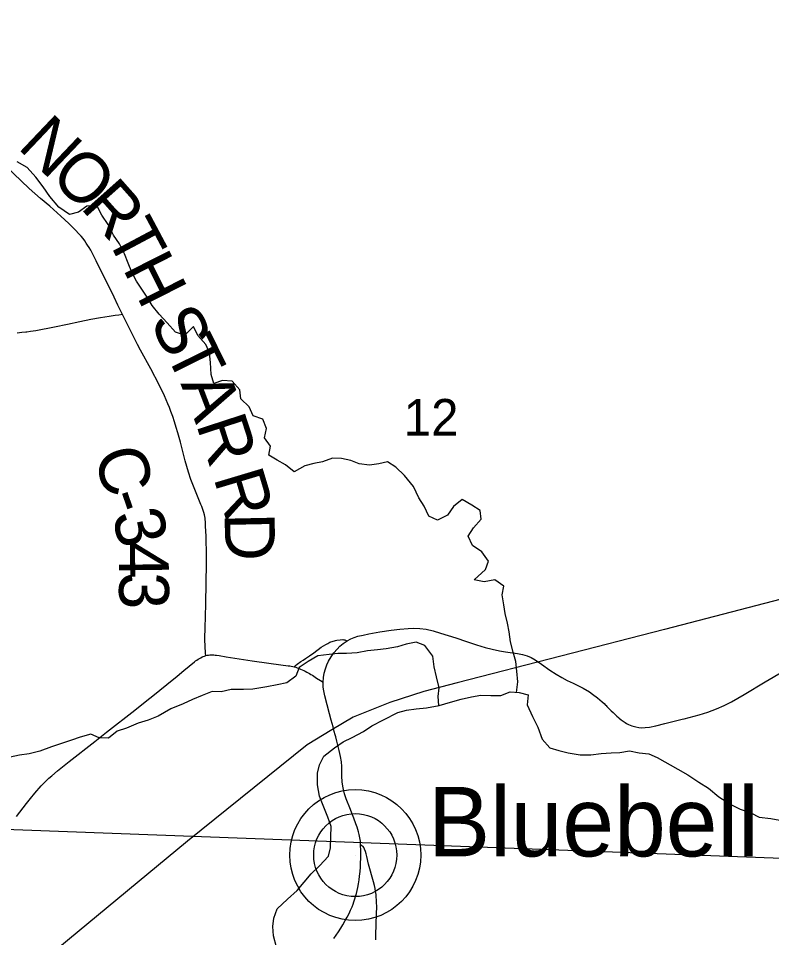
# Model space of a CAD drawing. Extents: x 0 to 34, y 0 to 22.
# Drawn here: x 26.138 to 26.994, y 18.613 to 19.658 of the extents above; entities that cross this region are included whole.
import ezdxf

# ---------------------------------------------------------------- set-up
doc = ezdxf.new("R2010")
doc.units = 0
for name, color, linetype in [('GM_X_Corporation', 7, 'Continuous'), ('GM_X_County_Road', 7, 'Continuous'), ('GM_X_County_Road_Text', 7, 'Continuous'), ('GM_X_Minor_River', 7, 'Continuous'), ('GM_X_Rail_Line', 7, 'Continuous'), ('GM_X_Section_Text', 7, 'Continuous'), ('GM_X_State_Route', 7, 'Continuous'), ('GM_X_Township_Road', 7, 'Continuous'), ('GM_X_Unincorporated', 7, 'Continuous'), ('GM_X_Unincorporated_Location', 7, 'Continuous'), ('GM_X_Unincorporated_Text', 7, 'Continuous')]:
    doc.layers.add(name, color=color, linetype=linetype)

msp = doc.modelspace()

# ---------------------------------------------------------------- linework, layer by layer
at = {"layer": 'GM_X_Corporation'}
msp.add_lwpolyline([(27.1321, 19.6957), (27.1305, 19.6616), (27.1072, 18.6988), (26.0916, 18.7368), (26.1009, 19.7362)], close=True, dxfattribs=at)
at = {"layer": 'GM_X_County_Road'}
for points in [[(26.2561, 19.3208), (26.2507, 19.3315), (26.2464, 19.3405), (26.2263, 19.3818), (26.2226, 19.3889), (26.2199, 19.3939), (26.2182, 19.397), (26.2164, 19.3999), (26.2149, 19.4022), (26.2132, 19.4045), (26.2112, 19.4072), (26.2089, 19.4099), (26.2061, 19.413), (26.203, 19.4164), (26.1951, 19.4244), (26.186, 19.4329), (26.1734, 19.4439), (26.163, 19.4528), (26.1499, 19.4643), (26.1233, 19.4897)], [(26.2561, 19.3208), (26.2518, 19.3203), (26.2477, 19.3197), (26.241, 19.3188), (26.2312, 19.3172), (26.2202, 19.3151), (26.2074, 19.3125), (26.1935, 19.3096), (26.1789, 19.3067), (26.1576, 19.3025), (26.1515, 19.3016), (26.1472, 19.301), (26.146, 19.3008), (26.1417, 19.3003), (26.1364, 19.2998)], [(26.3508, 18.9331), (26.3505, 18.9359), (26.3503, 18.9387), (26.3501, 18.9413), (26.35, 18.9448), (26.3498, 18.9504), (26.3498, 18.9547), (26.3499, 18.9627), (26.3505, 18.9794), (26.3508, 18.99), (26.3512, 19.0176), (26.3514, 19.0355), (26.3514, 19.0529), (26.3513, 19.0622), (26.3511, 19.069), (26.3508, 19.0747), (26.3505, 19.0803), (26.3503, 19.0857), (26.3501, 19.0876), (26.35, 19.0894), (26.3496, 19.0913), (26.3492, 19.0933), (26.3485, 19.0957), (26.3478, 19.0981), (26.347, 19.1002), (26.3461, 19.1027), (26.3452, 19.1051), (26.3421, 19.1125), (26.3389, 19.12), (26.3338, 19.1333), (26.3311, 19.1416), (26.3273, 19.1546), (26.3219, 19.1757), (26.319, 19.1865), (26.3172, 19.1926), (26.3151, 19.199), (26.3131, 19.205), (26.3111, 19.2108), (26.3094, 19.2153), (26.3077, 19.2195), (26.3037, 19.2286), (26.2976, 19.241), (26.2881, 19.2591), (26.2766, 19.2805), (26.2732, 19.287), (26.2659, 19.3014), (26.2614, 19.3102), (26.2561, 19.3208)], [(26.4511, 18.9205), (26.4526, 18.9218), (26.4544, 18.9233), (26.4562, 18.9247), (26.4574, 18.9255), (26.4586, 18.9263), (26.4612, 18.9279), (26.4639, 18.9297), (26.4687, 18.933), (26.4735, 18.9365), (26.482, 18.9426), (26.4872, 18.9458), (26.4895, 18.9471), (26.4906, 18.9477), (26.4917, 18.9483), (26.493, 18.9488), (26.4943, 18.9493), (26.4956, 18.9497), (26.4969, 18.9501), (26.4983, 18.9504), (26.4997, 18.9508), (26.5034, 18.9512), (26.5064, 18.9513), (26.5076, 18.9512), (26.5089, 18.951), (26.5103, 18.9505), (26.5115, 18.9501)], [(26.1354, 18.7502), (26.147, 18.7651), (26.1516, 18.7709), (26.1564, 18.7767), (26.1638, 18.785), (26.1698, 18.7912), (26.1725, 18.7938), (26.1757, 18.7966), (26.1823, 18.8023), (26.1954, 18.8127), (26.2247, 18.8357), (26.2379, 18.846), (26.2702, 18.8713), (26.2838, 18.8821), (26.2907, 18.8875), (26.3066, 18.9004), (26.3181, 18.9098), (26.3258, 18.9162), (26.3378, 18.926), (26.3392, 18.9271), (26.3406, 18.9281), (26.342, 18.9291), (26.3435, 18.93), (26.3449, 18.9308), (26.3465, 18.9316), (26.3478, 18.9321), (26.3491, 18.9326), (26.3508, 18.9331)], [(26.3508, 18.9331), (26.3523, 18.9335), (26.3539, 18.9337), (26.3553, 18.9339), (26.3567, 18.934), (26.3582, 18.934), (26.3598, 18.9339), (26.3613, 18.9337), (26.3627, 18.9335), (26.366, 18.9331), (26.374, 18.9319), (26.4034, 18.9273), (26.4388, 18.9224), (26.4416, 18.9221), (26.4445, 18.9217), (26.4462, 18.9215), (26.4478, 18.9212), (26.4495, 18.9209), (26.4511, 18.9205)], [(26.4511, 18.9205), (26.4529, 18.9199), (26.4547, 18.9193), (26.4567, 18.9185), (26.4584, 18.9177), (26.4602, 18.917), (26.4621, 18.9161), (26.4638, 18.9153), (26.4654, 18.9145), (26.4671, 18.9136), (26.4687, 18.9127), (26.4702, 18.9118), (26.4719, 18.9109), (26.4734, 18.9099), (26.4752, 18.9087), (26.4767, 18.9077), (26.4812, 18.9048), (26.4841, 18.9029)]]:
    msp.add_lwpolyline(points, dxfattribs=at)
at = {"layer": 'GM_X_Minor_River'}
for points in [[(26.7039, 18.8914), (26.7054, 18.9032), (26.7042, 18.9153), (26.703, 18.9263), (26.7002, 18.9372), (26.6971, 18.9489), (26.6955, 18.9603), (26.6935, 18.9701), (26.6911, 18.9811), (26.6895, 18.9909), (26.6876, 19.0023), (26.6894, 19.0121), (26.6791, 19.0192), (26.667, 19.0172), (26.6557, 19.0194), (26.6688, 19.0312), (26.6721, 19.0407), (26.6645, 19.0513), (26.6538, 19.0584), (26.6488, 19.0689), (26.6548, 19.0784), (26.6637, 19.0884), (26.6625, 19.0982), (26.653, 19.1042), (26.642, 19.1105), (26.6322, 19.1028), (26.6255, 19.0929), (26.6139, 19.0871), (26.6044, 19.0916), (26.599, 19.1029), (26.5929, 19.1127), (26.5867, 19.1255), (26.5764, 19.1379), (26.5668, 19.1472), (26.5573, 19.1536), (26.5472, 19.1512), (26.5366, 19.1496), (26.5252, 19.151), (26.5154, 19.155), (26.5048, 19.1572), (26.4949, 19.1575), (26.4832, 19.1536), (26.4734, 19.1516), (26.4633, 19.1488), (26.4512, 19.1419), (26.4413, 19.1501), (26.4318, 19.1553), (26.4223, 19.1612), (26.4241, 19.1711), (26.4176, 19.1809), (26.4198, 19.1915), (26.4155, 19.2021), (26.4045, 19.2058), (26.3999, 19.216), (26.3904, 19.2249), (26.3895, 19.2352), (26.3808, 19.2453), (26.3698, 19.2459), (26.36, 19.2424), (26.3569, 19.2526), (26.356, 19.2663), (26.3548, 19.2772), (26.3509, 19.287), (26.3417, 19.2972), (26.3367, 19.3074), (26.327, 19.2974), (26.3164, 19.3007), (26.3068, 19.3116), (26.2977, 19.3213), (26.2897, 19.3311), (26.2835, 19.3417), (26.272, 19.359), (26.2667, 19.3691), (26.2624, 19.3793), (26.2585, 19.3899), (26.2528, 19.4012), (26.2459, 19.411), (26.2397, 19.4234), (26.2324, 19.4339), (26.2267, 19.4449), (26.2157, 19.444), (26.206, 19.4371), (26.1958, 19.4347), (26.1836, 19.4429), (26.1733, 19.4549), (26.166, 19.4662), (26.1576, 19.4771), (26.1477, 19.488), (26.1363, 19.4943)], [(26.6157, 18.8764), (26.6149, 18.8867), (26.6159, 18.8966), (26.6131, 18.909), (26.6104, 18.9204), (26.6088, 18.9325), (26.5996, 18.9445), (26.5897, 18.9486), (26.5784, 18.9462), (26.5686, 18.943), (26.5558, 18.941), (26.546, 18.9398), (26.5346, 18.9385), (26.5229, 18.9365), (26.5105, 18.9356), (26.5006, 18.9355), (26.4908, 18.9346), (26.478, 18.933), (26.4671, 18.9264), (26.4569, 18.9195), (26.4532, 18.9096), (26.4427, 18.9023), (26.4318, 18.8999), (26.4201, 18.8975), (26.4042, 18.8951), (26.3936, 18.8946), (26.3797, 18.8945), (26.3683, 18.8921), (26.3581, 18.8923), (26.3465, 18.8877), (26.3355, 18.8834), (26.325, 18.8783), (26.3111, 18.8725), (26.2964, 18.8644), (26.2851, 18.8597), (26.2738, 18.8562), (26.2606, 18.8508), (26.25, 18.8473), (26.2403, 18.8392), (26.2297, 18.8398), (26.2202, 18.8439), (26.2081, 18.8404), (26.198, 18.8372), (26.1753, 18.8294), (26.1622, 18.8247), (26.1501, 18.8216), (26.1388, 18.8199), (26.1282, 18.8176)], [(26.431, 18.6018), (26.4275, 18.6146), (26.427, 18.6252), (26.428, 18.6347), (26.4317, 18.6453), (26.4434, 18.6564), (26.4546, 18.666), (26.4703, 18.6851), (26.4801, 18.6943), (26.4902, 18.705), (26.4924, 18.7145), (26.493, 18.7271), (26.4933, 18.7388), (26.4894, 18.7494), (26.484, 18.7626), (26.4801, 18.7735), (26.4778, 18.7864), (26.4776, 18.7996), (26.4798, 18.8091), (26.4847, 18.819), (26.497, 18.8282), (26.5068, 18.8352), (26.517, 18.8402), (26.5298, 18.8468), (26.5395, 18.8533), (26.5527, 18.8603), (26.5689, 18.8684), (26.5787, 18.8712), (26.59, 18.8728), (26.6017, 18.8737), (26.6161, 18.8765), (26.6289, 18.8804), (26.641, 18.8836), (26.6527, 18.8863), (26.6632, 18.888), (26.6746, 18.8877), (26.6859, 18.8878), (26.6968, 18.8921), (26.7067, 18.8911), (26.7173, 18.8885), (26.7159, 18.8772), (26.722, 18.864), (26.7282, 18.8519), (26.7332, 18.8383), (26.7416, 18.8285), (26.7519, 18.8252), (26.7625, 18.8227), (26.7761, 18.8202), (26.7882, 18.8203), (26.7999, 18.822), (26.8116, 18.8225), (26.8214, 18.8229), (26.8324, 18.825), (26.8434, 18.8228), (26.8543, 18.8214), (26.8638, 18.8173), (26.8874, 18.8039), (26.8984, 18.7976), (26.9109, 18.7894), (26.922, 18.7823), (26.9338, 18.7726), (26.9474, 18.764), (26.9581, 18.7585), (26.9702, 18.7544), (26.9797, 18.7496), (26.9929, 18.7478), (27.0032, 18.7461)]]:
    msp.add_lwpolyline(points, dxfattribs=at)
at = {"layer": 'GM_X_Rail_Line'}
msp.add_lwpolyline([(27.3181, 19.0787), (26.8719, 18.963), (26.6364, 18.9022), (26.5984, 18.8925), (26.5599, 18.88), (26.5181, 18.863), (26.4939, 18.8489), (26.4659, 18.8316), (26.3299, 18.7221), (25.6255, 18.1395), (25.5717, 18.0909), (25.5316, 18.0529), (25.4885, 18.0044), (25.4477, 17.9591), (25.4146, 17.9181), (25.3806, 17.8712), (24.8603, 17.1266), (24.3577, 16.4125), (24.3204, 16.3658), (24.2794, 16.3248), (24.2417, 16.292), (23.9897, 16.0983), (23.6678, 15.8432), (23.5167, 15.7235)], dxfattribs=at)
at = {"layer": 'GM_X_State_Route'}
msp.add_lwpolyline([(26.4962, 18.6115), (26.499, 18.6155), (26.5015, 18.6192), (26.5041, 18.6233), (26.5065, 18.6272), (26.5092, 18.6319), (26.5113, 18.6358), (26.5135, 18.6401), (26.5152, 18.6438), (26.5169, 18.6475), (26.5181, 18.6505), (26.5191, 18.6534), (26.5201, 18.6565), (26.521, 18.6593), (26.5219, 18.6626), (26.5227, 18.666), (26.5235, 18.6697), (26.5243, 18.6739), (26.525, 18.6784), (26.5255, 18.6826), (26.526, 18.6877), (26.5264, 18.6925), (26.5267, 18.6974), (26.5269, 18.7025), (26.527, 18.7069), (26.5269, 18.7113), (26.5266, 18.7179), (26.5264, 18.7223), (26.5258, 18.7261), (26.525, 18.7297), (26.5242, 18.7327), (26.5226, 18.738), (26.5212, 18.7421), (26.5189, 18.7484), (26.5166, 18.7542), (26.515, 18.7582), (26.5102, 18.7703), (26.5082, 18.7762), (26.5067, 18.7829), (26.5058, 18.7891), (26.5055, 18.7965), (26.5053, 18.807), (26.5048, 18.8125), (26.5038, 18.8185), (26.5024, 18.8251), (26.4997, 18.8359), (26.4984, 18.8407), (26.4977, 18.8431), (26.4968, 18.8467), (26.4953, 18.852), (26.4932, 18.8598), (26.4913, 18.867), (26.4885, 18.8772), (26.4859, 18.8875), (26.4849, 18.8931), (26.4843, 18.8974), (26.4841, 18.9029), (26.4844, 18.9082), (26.4853, 18.9131), (26.4866, 18.918), (26.4884, 18.9228), (26.4903, 18.9267), (26.4931, 18.9317), (26.4964, 18.9363), (26.5001, 18.9406), (26.5032, 18.9438), (26.507, 18.9471), (26.5115, 18.9501), (26.5157, 18.9523), (26.5192, 18.9538), (26.5234, 18.9551), (26.5295, 18.9565), (26.5362, 18.9578), (26.5485, 18.96), (26.5614, 18.9621), (26.5713, 18.9633), (26.5807, 18.964), (26.5869, 18.9642), (26.5938, 18.964), (26.6013, 18.9631), (26.6092, 18.9613), (26.6176, 18.9588), (26.6348, 18.9533), (26.6472, 18.9491), (26.6583, 18.9454), (26.6684, 18.9422), (26.6762, 18.9403), (26.6847, 18.9386), (26.6914, 18.9375), (26.7049, 18.9354), (26.7105, 18.9344), (26.7159, 18.9329), (26.7206, 18.931), (26.725, 18.9285), (26.7323, 18.9235), (26.7418, 18.9166), (26.749, 18.9119), (26.7554, 18.9081), (26.7614, 18.905), (26.7681, 18.9018), (26.772, 18.9), (26.7743, 18.8989), (26.7798, 18.896), (26.7868, 18.8918), (26.7904, 18.8893), (26.7959, 18.8852), (26.8011, 18.8807), (26.8034, 18.8786), (26.805, 18.877), (26.8057, 18.8763), (26.8066, 18.8752), (26.8094, 18.8723), (26.8107, 18.8711), (26.8115, 18.8704), (26.8136, 18.8683), (26.8171, 18.8651), (26.818, 18.8643), (26.8198, 18.8627), (26.8207, 18.862), (26.823, 18.8601), (26.8249, 18.8587), (26.8273, 18.857), (26.8289, 18.8561), (26.831, 18.855), (26.8348, 18.8535), (26.8365, 18.8529), (26.8394, 18.8521), (26.8429, 18.8515), (26.8464, 18.8512), (26.85, 18.8513), (26.8549, 18.8519), (26.8621, 18.8534), (26.8724, 18.8559), (26.8862, 18.8593), (26.8922, 18.8608), (26.8946, 18.8614), (26.9114, 18.8659), (26.9215, 18.869), (26.9313, 18.8726), (26.9398, 18.8764), (26.9481, 18.8806), (26.9626, 18.8889), (26.9866, 18.9032), (27.0064, 18.915)], dxfattribs=at)
at = {"layer": 'GM_X_Township_Road'}
msp.add_lwpolyline([(26.5439, 18.61), (26.5441, 18.6176), (26.5443, 18.6254), (26.5449, 18.6419), (26.545, 18.6453), (26.545, 18.6486), (26.5449, 18.6517), (26.5447, 18.6554), (26.5445, 18.6586), (26.5442, 18.6615), (26.5437, 18.6649), (26.5432, 18.6683), (26.5423, 18.672), (26.5413, 18.6758), (26.5357, 18.6959), (26.5336, 18.7049), (26.5329, 18.7077), (26.5321, 18.7103), (26.5311, 18.7133), (26.5303, 18.715), (26.5296, 18.716), (26.5282, 18.7171), (26.5266, 18.7179)], dxfattribs=at)
at = {"layer": 'GM_X_Unincorporated'}
for radius in [0.0744, 0.0472]:
    msp.add_circle((26.5206, 18.7064), radius, dxfattribs=at)
at = {"layer": 'GM_X_Unincorporated_Location'}
msp.add_line((26.5206, 18.7064), (26.5206, 18.7064), dxfattribs=at)

# ---------------------------------------------------------------- texts
at = {"layer": 'GM_X_County_Road_Text'}
for s, rotation, p in [('N', 316.4633, (26.1355, 19.5107)), ('O', 316.4026, (26.1717, 19.4763)), ('R', 311.6089, (26.2071, 19.4427)), ('T', 298.0218, (26.236, 19.4107)), ('H', 296.8379, (26.2558, 19.3735)), ('S', 296.8062, (26.2863, 19.3133)), ('T', 296.3025, (26.3035, 19.2792)), ('A', 290.8767, (26.3218, 19.2424)), ('R', 288.0888, (26.3394, 19.1964)), ('C', 285.3943, (26.2233, 19.1629)), ('R', 286.6981, (26.3592, 19.1357)), ('-', 288.9757, (26.2368, 19.1142)), ('3', 283.2903, (26.244, 19.0936)), ('D', 271.2131, (26.372, 19.095)), ('4', 270.6297, (26.2516, 19.0628)), ('3', 270.4944, (26.252, 19.0279))]:
    msp.add_text(s, height=0.0568, rotation=rotation, dxfattribs=at).set_placement(p)
at = {"layer": 'GM_X_Section_Text'}
msp.add_text('12', height=0.04186, rotation=0, dxfattribs=at).set_placement((26.5757, 19.183))
at = {"layer": 'GM_X_Unincorporated_Text'}
msp.add_text('Bluebell', height=0.07898, rotation=0, dxfattribs=at).set_placement((26.6034, 18.7049))

doc.saveas('drawing.dxf')
